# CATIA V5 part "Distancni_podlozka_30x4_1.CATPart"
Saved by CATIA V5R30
Part number: Dosedaci_podlozka_30x4_1
Definition: E 1500_30x4_2
Nomenclature: E 1500_30x4_2
Source: Unknown
Description: PART--DESC
Bounding box of the stored display mesh (mm): x 189 to 219, y 75 to 105, z -224 to -220
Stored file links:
  E:\Bakalarka\Model\Forma_v7\Distancni_podlozka_30x4_1.CATPart
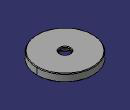
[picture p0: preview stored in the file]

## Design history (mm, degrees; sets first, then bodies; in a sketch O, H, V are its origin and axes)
Body1 "MANIFOLD_SOLID_BREP #4066" (main body)
  Solid1: solid without history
